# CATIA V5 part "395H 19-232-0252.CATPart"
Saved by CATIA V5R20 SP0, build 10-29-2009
Part number: 395H 19-232-0252
Source: Unknown
Bounding box of the stored display mesh (mm): x -36.37 to 36.37, y -36.37 to 36.37, z -80 to 20
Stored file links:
  C:\Users\Utente\Desktop\3D files 395H FCA\395H 19-232-0252.CATPart
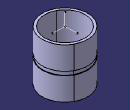
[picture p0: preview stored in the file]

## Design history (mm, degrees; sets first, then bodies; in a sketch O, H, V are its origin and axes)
Set1
  Line1 to Line3: stored without definition
  Point1 "Punto.4": stored without definition
Body1 (main body)
  Solid1 "PartBody": solid without history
